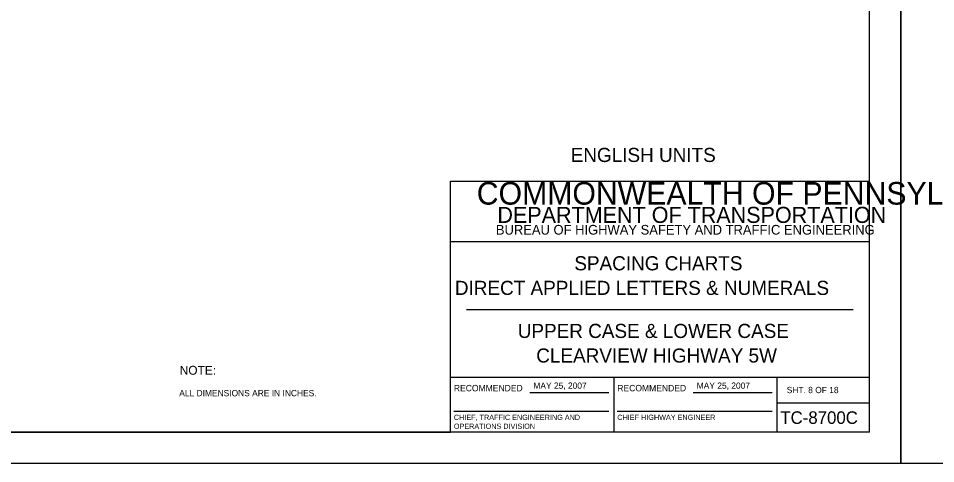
# Model space of a CAD drawing. Extents: x 637580 to 641849, y 297270 to 299646.
# Drawn here: x 638841.2 to 639278.9, y 297269.6 to 297482.3 of the extents above; entities that cross this region are included whole.
import ezdxf

# ---------------------------------------------------------------- set-up
doc = ezdxf.new("R2010")
doc.units = 0
for name, color, linetype in [('1', 7, 'Continuous'), ('2', 7, 'Continuous'), ('XCS-GRID-HVGL', 7, 'Continuous')]:
    doc.layers.add(name, color=color, linetype=linetype)

msp = doc.modelspace()

# ---------------------------------------------------------------- linework, layer by layer
at = {"layer": '1'}
for p, q in [((639247.31, 297284.63), (639247.31, 297848.63)), ((639047.31, 297284.63), (639047.31, 297404.63)), ((639047.31, 297404.63), (639247.31, 297404.63)), ((639247.31, 297375.63), (639047.31, 297375.63)), ((639055.06, 297343.31), (639239.56, 297343.31)), ((639047.31, 297311), (639247.31, 297311)), ((639125.31, 297311), (639125.31, 297284.63)), ((639203.19, 297284.63), (639203.19, 297311)), ((639085.24, 297303.57), (639122.87, 297303.57)), ((639163.24, 297303.57), (639200.87, 297303.57)), ((639203.19, 297298.63), (639247.31, 297298.63)), ((639048.99, 297294.68), (639122.87, 297294.68)), ((639126.99, 297294.68), (639200.87, 297294.68)), ((639247.31, 297284.63), (638461.31, 297284.63)), ((638461.31, 297284.63), (639047.31, 297284.63))]:
    msp.add_line(p, q, dxfattribs=at)
at = {"layer": 'XCS-GRID-HVGL'}
for points in [[(638421.31, 297863.63), (639262.31, 297863.63), (639262.31, 297269.63), (638421.31, 297269.63)], [(639262.31, 297863.63), (640103.31, 297863.63), (640103.31, 297269.63), (639262.31, 297269.63)]]:
    msp.add_lwpolyline(points, close=True, dxfattribs=at)

# ---------------------------------------------------------------- texts
at = {"layer": '1'}
for s, height, p in [('COMMONWEALTH OF PENNSYLVANIA', 10.7828, (639059.9, 297393.36)), ('DEPARTMENT OF TRANSPORTATION', 7.6837, (639069.76, 297384.61)), ('BUREAU OF HIGHWAY SAFETY AND TRAFFIC ENGINEERING', 4.6253, (639069.04, 297379.04)), ('SPACING CHARTS', 6.75, (639106.47, 297361.97)), ('DIRECT APPLIED LETTERS & NUMERALS', 6.75, (639049.47, 297350.22)), ('UPPER CASE & LOWER CASE', 6.75, (639079.47, 297329.66)), ('CLEARVIEW HIGHWAY 5W', 6.75, (639088.3, 297317.91)), ('RECOMMENDED', 3.048, (639048.99, 297304.2)), ('RECOMMENDED', 3.048, (639126.99, 297304.2)), ('SHT. 8 OF 18', 3, (639207.82, 297303.31)), ('CHIEF, TRAFFIC ENGINEERING AND', 2.5, (639048.99, 297290.51)), ('CHIEF HIGHWAY ENGINEER', 2.5, (639126.99, 297290.51)), ('TC-8700C', 6, (639204.77, 297288.63)), ('OPERATIONS DIVISION', 2.5, (639048.99, 297286.26))]:
    msp.add_text(s, height=height, dxfattribs=at).set_placement(p)
at = {"layer": '2'}
for s, height, p in [('ENGLISH UNITS', 6.75, (639104.74, 297413.72)), ('NOTE:', 4.25, (638918.16, 297312.1)), ('MAY 25, 2007', 3, (639086.93, 297305.39)), ('ALL DIMENSIONS ARE IN INCHES.', 3, (638917.94, 297301.83))]:
    msp.add_text(s, height=height, dxfattribs=at).set_placement(p)
msp.add_text('MAY 25, 2007', height=3, rotation=360, dxfattribs=at).set_placement((639164.88, 297305.39))

doc.saveas('drawing.dxf')
